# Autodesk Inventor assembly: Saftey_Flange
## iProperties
Shininess: 64.0
Length Units: 11269
Angle Units: 11279
Time Units: 11290
Mass Units: 11283
Length Display Precision: 3
Angle Display Precision: 2
Compacted: True
Created: 2004-07
Part Number: Saftey_Flange
Document SubType Name: Assembly
Designer: John Blackburn
Manufacturer: Standard
Standards Organization: Custom
Density: 0.0
Volumn: 0.0
Area: 0.0
PropertySet Name: Model Information
Control State: 0
Master: False
Checked Out: False
Author: John Blackburn
